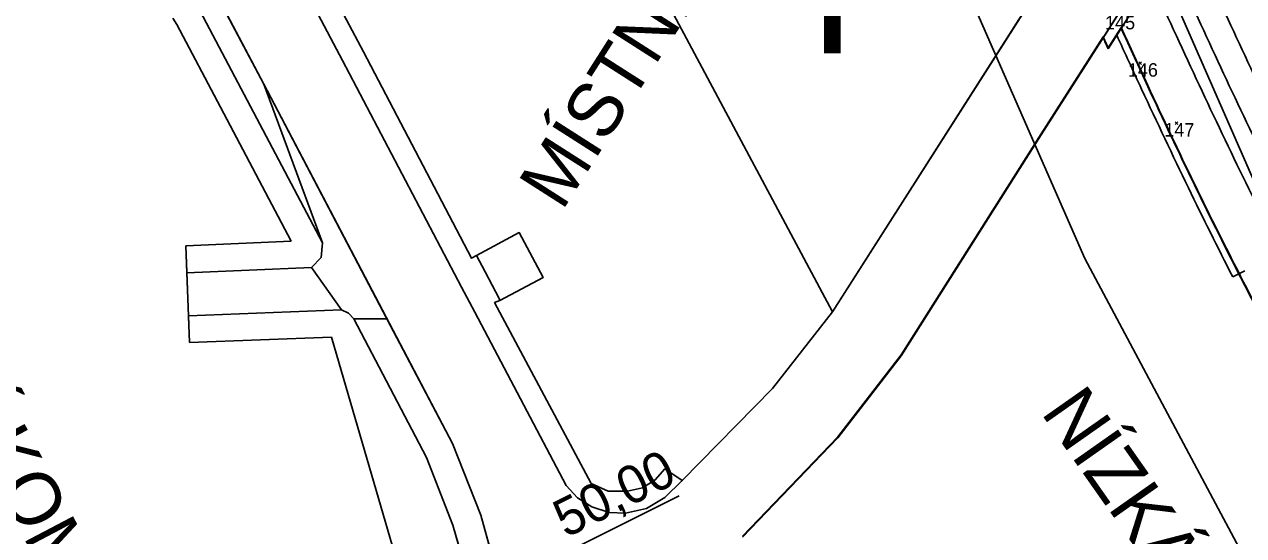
# Model space of a CAD drawing. Extents: x -606444 to -604546, y -1158114 to -1156869.
# Drawn here: x -605195.8 to -605105.4, y -1157370.5 to -1157332.6 of the extents above; entities that cross this region are included whole.
import ezdxf

# ---------------------------------------------------------------- set-up
doc = ezdxf.new("R2010")
doc.units = 0
for name, color, linetype in [('B_CHOD', 7, 'Continuous'), ('B_TRAM', 7, 'Continuous'), ('B_VOZ', 7, 'Continuous'), ('B_ZELEN', 7, 'Continuous'), ('geofyzikální profily_předběžný GTP', 7, 'Continuous'), ('NS_VB', 7, 'Continuous'), ('NS_VB_OBJ', 7, 'Continuous'), ('NS_VB_POP', 7, 'Continuous'), ('OSA', 7, 'Continuous'), ('OSAPOP', 7, 'Continuous'), ('podélný profil trasou tramvaje', 7, 'Continuous'), ('stabilitní profily_předběžný GTP', 7, 'Continuous')]:
    doc.layers.add(name, color=color, linetype=linetype)

msp = doc.modelspace()

# ---------------------------------------------------------------- linework, layer by layer
for p, q in [((-605113.04, -1157335.43), (-605113.14, -1157335.33)), ((-605113.04, -1157335.43), (-605113.14, -1157335.53)), ((-605113.04, -1157335.43), (-605112.94, -1157335.33)), ((-605113.04, -1157335.43), (-605112.94, -1157335.53)), ((-605110.36, -1157339.87), (-605110.46, -1157339.77)), ((-605110.36, -1157339.87), (-605110.46, -1157339.97)), ((-605110.36, -1157339.87), (-605110.26, -1157339.77)), ((-605110.36, -1157339.87), (-605110.26, -1157339.97))]:
    msp.add_line(p, q)
at = {"layer": 'B_CHOD'}
for points in [[(-605179.53, -1157337.76), (-605173.71, -1157348.76), (-605178.07, -1157336.98), (-605182.29, -1157328.99), (-605188.69, -1157318.53), (-605191.523, -1157314.683), (-605192.834, -1157315.649), (-605190.17, -1157319.29), (-605183.11, -1157331.05), (-605182.79, -1157331.58), (-605179.53, -1157337.76)], [(-605110.093, -1157324.593), (-605115.8, -1157333.547)], [(-605115.427, -1157334.358), (-605109.46, -1157324.996)], [(-605160.95, -1157353.18), (-605160.55, -1157353.02), (-605160.62, -1157352.89), (-605161.66, -1157350.91), (-605162.3, -1157349.7), (-605162.66, -1157349.9), (-605170.68, -1157334.59), (-605172.783, -1157330.604)], [(-605174.263, -1157331.396), (-605172.24, -1157335.22), (-605163.4, -1157352.04), (-605162.42, -1157353.9), (-605155.63, -1157366.76), (-605154.79, -1157367.67), (-605153.74, -1157368.34), (-605152.44, -1157368.76), (-605151.23, -1157368.79), (-605149.67, -1157368.45), (-605148.32, -1157367.65), (-605147.03, -1157366.39), (-605148.31, -1157365.52), (-605149.03, -1157366.34), (-605149.97, -1157366.92), (-605151.083, -1157367.17), (-605152.52, -1157367.17), (-605153.78, -1157366.59), (-605160.95, -1157353.18)], [(-605173.82, -1157349.84), (-605174.53, -1157350.57), (-605172.3, -1157353.72), (-605171.79, -1157353.96), (-605171.4, -1157354.38), (-605168.939, -1157354.38), (-605178.07, -1157336.98), (-605173.71, -1157348.76), (-605173.82, -1157349.84)], [(-605157.35, -1157351.33), (-605159.13, -1157347.99), (-605162.3, -1157349.7), (-605161.66, -1157350.91), (-605160.62, -1157352.89), (-605160.55, -1157353.02), (-605157.35, -1157351.33)], [(-605183.658, -1157354.155), (-605172.3, -1157353.72), (-605174.53, -1157350.57), (-605183.78, -1157350.98), (-605183.658, -1157354.155)], [(-605164.08, -1157363.64), (-605168.939, -1157354.38), (-605171.4, -1157354.38), (-605166.01, -1157364.66), (-605164.04, -1157369.69), (-605162.76, -1157374.11)], [(-605160.55, -1157374.03), (-605161.97, -1157368.95), (-605164.08, -1157363.64)]]:
    msp.add_lwpolyline(points, dxfattribs=at)
msp.add_arc((-604045.754, -1156842.066), 1177.52, 204.669736, 204.713151, dxfattribs=at)
at = {"layer": 'B_TRAM'}
msp.add_line((-605114.467, -1157332.852), (-605109.46, -1157324.996), dxfattribs=at)
for centre, radius, start, end in [((-603789.869, -1156724.367), 1457.674, 204.672767, 204.858777), ((-604698.868, -1157145.516), 455.853, 204.85878, 205.87559), ((-604812.368, -1157200.569), 329.706, 205.87559, 207.29075), ((-604908.165, -1157249.994), 221.911, 207.29075, 209.40677)]:
    msp.add_arc(centre, radius, start, end, dxfattribs=at)
at = {"layer": 'B_VOZ'}
for points in [[(-605186.716, -1157311.143), (-605191.523, -1157314.683), (-605188.69, -1157318.53), (-605182.29, -1157328.99), (-605178.07, -1157336.98), (-605164.08, -1157363.64), (-605161.97, -1157368.95), (-605160.55, -1157374.03)], [(-605107.824, -1157321.827), (-605110.697, -1157314.376), (-605135.867, -1157353.871), (-605140.32, -1157359.56), (-605147.03, -1157366.39), (-605148.32, -1157367.65), (-605149.67, -1157368.45), (-605151.23, -1157368.79), (-605152.44, -1157368.76), (-605153.74, -1157368.34), (-605154.79, -1157367.67), (-605155.63, -1157366.76), (-605162.42, -1157353.9), (-605163.4, -1157352.04), (-605172.24, -1157335.22), (-605174.263, -1157331.396)], [(-605142.56, -1157370.59), (-605135.48, -1157363.22), (-605130.78, -1157357.13), (-605120.39, -1157340.75), (-605110.093, -1157324.593)]]:
    msp.add_lwpolyline(points, dxfattribs=at)
at = {"layer": 'B_ZELEN'}
for p, q in [((-605179.53, -1157337.76), (-605182.79, -1157331.58)), ((-605184.823, -1157332.082), (-605184.532, -1157332.564)), ((-605184.532, -1157332.564), (-605181.298, -1157338.694)), ((-605115.426, -1157334.283), (-605114.467, -1157332.778)), ((-605120.389, -1157340.675), (-605115.799, -1157333.473)), ((-605115.799, -1157333.473), (-605115.426, -1157334.283)), ((-605173.71, -1157348.76), (-605179.53, -1157337.76)), ((-605181.298, -1157338.694), (-605176.039, -1157348.635)), ((-605130.779, -1157357.055), (-605120.389, -1157340.675)), ((-605176.039, -1157348.635), (-605183.857, -1157348.981)), ((-605183.857, -1157348.981), (-605183.78, -1157350.98)), ((-605173.82, -1157349.84), (-605173.71, -1157348.76)), ((-605174.53, -1157350.57), (-605173.82, -1157349.84)), ((-605183.78, -1157350.98), (-605174.53, -1157350.57)), ((-605172.3, -1157353.72), (-605183.658, -1157354.155)), ((-605183.658, -1157354.155), (-605183.582, -1157356.154)), ((-605171.79, -1157353.96), (-605172.3, -1157353.72)), ((-605171.4, -1157354.38), (-605171.79, -1157353.96)), ((-605166.01, -1157364.66), (-605171.4, -1157354.38)), ((-605183.582, -1157356.154), (-605173.042, -1157355.75)), ((-605173.042, -1157355.75), (-605167.056, -1157376.238)), ((-605135.479, -1157363.145), (-605130.779, -1157357.055)), ((-605142.559, -1157370.515), (-605135.479, -1157363.145)), ((-605164.04, -1157369.69), (-605166.01, -1157364.66)), ((-605162.76, -1157374.11), (-605164.04, -1157369.69))]:
    msp.add_line(p, q, dxfattribs=at)
for points in [[(-605156.956, -1157314.418), (-605135.867, -1157353.871), (-605118.771, -1157327.046), (-605119.142, -1157326.233), (-605118.182, -1157324.725), (-605145.901, -1157264.009), (-605144.283, -1157284.607)], [(-605140.32, -1157359.56), (-605135.867, -1157353.871), (-605156.956, -1157314.418), (-605169.829, -1157321.13)], [(-605172.783, -1157330.604), (-605170.68, -1157334.59), (-605162.66, -1157349.9), (-605162.3, -1157349.7), (-605159.13, -1157347.99), (-605157.35, -1157351.33), (-605160.55, -1157353.02), (-605160.95, -1157353.18), (-605153.78, -1157366.59), (-605152.52, -1157367.17), (-605151.083, -1157367.17), (-605149.97, -1157366.92), (-605149.03, -1157366.34), (-605148.31, -1157365.52), (-605147.03, -1157366.39), (-605140.32, -1157359.56)]]:
    msp.add_lwpolyline(points, dxfattribs=at)
for centre, radius, start, end in [((-603124.644, -1156416.743), 2190.552, 204.719463, 204.843219), ((-604711.097, -1157151.24), 442.318, 204.84322, 205.89115), ((-604805.738, -1157197.177), 337.118, 205.89115, 207.2752), ((-604910.994, -1157251.446), 218.695, 207.2752, 209.42233)]:
    msp.add_arc(centre, radius, start, end, dxfattribs=at)
at = {"layer": 'geofyzikální profily_předběžný GTP'}
msp.add_lwpolyline([(-605668.887, -1157175.563), (-605638.047, -1157172.713), (-605616.091, -1157172.842), (-605512.92, -1157173.16), (-605468.488, -1157175.648), (-605413.499, -1157174.062), (-605313.444, -1157169.44), (-605274.571, -1157178.007), (-605221.389, -1157204.274), (-605178.573, -1157224.003), (-605160.32, -1157243.281), (-605143.644, -1157289.502), (-605117.165, -1157349.927), (-605096.208, -1157389.159), (-605065.898, -1157426.812), (-605053.52, -1157443.58), (-605045.82, -1157465.15), (-605020.205, -1157502.195)], dxfattribs=at)
at = {"layer": 'NS_VB'}
for p, q in [((-605135.867, -1157353.871), (-605110.697, -1157314.376)), ((-605120.39, -1157340.75), (-605110.093, -1157324.593)), ((-605115.427, -1157334.358), (-605109.46, -1157324.996)), ((-605182.29, -1157328.99), (-605178.07, -1157336.98)), ((-605172.778, -1157330.613), (-605170.68, -1157334.59)), ((-605179.53, -1157337.76), (-605182.79, -1157331.58)), ((-605172.24, -1157335.22), (-605174.263, -1157331.396)), ((-605184.532, -1157332.564), (-605184.823, -1157332.082)), ((-605181.298, -1157338.694), (-605184.532, -1157332.564)), ((-605170.68, -1157334.59), (-605162.66, -1157349.9)), ((-605163.4, -1157352.04), (-605172.24, -1157335.22)), ((-605178.07, -1157336.98), (-605164.08, -1157363.64)), ((-605173.71, -1157348.76), (-605179.53, -1157337.76)), ((-605176.039, -1157348.635), (-605181.298, -1157338.694)), ((-605120.39, -1157340.75), (-605130.78, -1157357.13)), ((-605162.3, -1157349.7), (-605159.13, -1157347.99)), ((-605159.13, -1157347.99), (-605157.35, -1157351.33)), ((-605183.857, -1157348.981), (-605176.039, -1157348.635)), ((-605183.857, -1157348.981), (-605183.582, -1157356.154)), ((-605173.82, -1157349.84), (-605173.71, -1157348.76)), ((-605174.53, -1157350.57), (-605173.82, -1157349.84)), ((-605162.66, -1157349.9), (-605162.3, -1157349.7)), ((-605162.3, -1157349.7), (-605161.66, -1157350.91)), ((-605183.78, -1157350.98), (-605174.53, -1157350.57)), ((-605161.66, -1157350.91), (-605160.62, -1157352.89)), ((-605157.35, -1157351.33), (-605160.55, -1157353.02)), ((-605162.42, -1157353.9), (-605163.4, -1157352.04)), ((-605160.55, -1157353.02), (-605160.95, -1157353.18)), ((-605160.95, -1157353.18), (-605153.78, -1157366.59)), ((-605160.62, -1157352.89), (-605160.55, -1157353.02)), ((-605172.3, -1157353.72), (-605183.658, -1157354.155)), ((-605171.79, -1157353.96), (-605172.3, -1157353.72)), ((-605171.4, -1157354.38), (-605171.79, -1157353.96)), ((-605166.01, -1157364.66), (-605171.4, -1157354.38)), ((-605155.63, -1157366.76), (-605162.42, -1157353.9)), ((-605135.867, -1157353.871), (-605140.32, -1157359.56)), ((-605173.042, -1157355.75), (-605183.582, -1157356.154)), ((-605173.042, -1157355.75), (-605167.056, -1157376.238)), ((-605130.78, -1157357.13), (-605135.48, -1157363.22)), ((-605140.32, -1157359.56), (-605147.03, -1157366.39)), ((-605135.48, -1157363.22), (-605142.56, -1157370.59)), ((-605164.08, -1157363.64), (-605161.97, -1157368.95)), ((-605164.04, -1157369.69), (-605166.01, -1157364.66)), ((-605149.03, -1157366.34), (-605148.31, -1157365.52)), ((-605148.31, -1157365.52), (-605147.03, -1157366.39)), ((-605154.79, -1157367.67), (-605155.63, -1157366.76)), ((-605153.78, -1157366.59), (-605152.52, -1157367.17)), ((-605152.52, -1157367.17), (-605151.083, -1157367.17)), ((-605151.083, -1157367.17), (-605149.97, -1157366.92)), ((-605149.97, -1157366.92), (-605149.03, -1157366.34)), ((-605147.03, -1157366.39), (-605148.32, -1157367.65)), ((-605153.74, -1157368.34), (-605154.79, -1157367.67)), ((-605148.32, -1157367.65), (-605149.67, -1157368.45)), ((-605161.97, -1157368.95), (-605160.55, -1157374.03)), ((-605152.44, -1157368.76), (-605153.74, -1157368.34)), ((-605151.23, -1157368.79), (-605152.44, -1157368.76)), ((-605149.67, -1157368.45), (-605151.23, -1157368.79)), ((-605162.76, -1157374.11), (-605164.04, -1157369.69))]:
    msp.add_line(p, q, dxfattribs=at)
for centre, radius, start, end in [((-604045.754, -1156842.066), 1177.52, 204.669736, 204.713151), ((-604045.754, -1156842.066), 1176.02, 204.666083, 204.896591), ((-604665.748, -1157129.813), 492.506, 204.89659, 205.83778), ((-604827.34, -1157208.061), 312.965, 205.83778, 207.32857), ((-604900.916, -1157246.083), 230.146, 207.32857, 209.36895)]:
    msp.add_arc(centre, radius, start, end, dxfattribs=at)
at = {"layer": 'NS_VB_OBJ'}
msp.add_lwpolyline([(-605106.176, -1157351.278), (-605105.286, -1157350.821)], dxfattribs=at)
for centre, radius, start, end in [((-604045.754, -1156842.066), 1176.52, 204.681788, 204.896591), ((-604665.748, -1157129.813), 493.006, 204.89659, 205.83778), ((-604827.34, -1157208.061), 313.465, 205.83778, 207.18615)]:
    msp.add_arc(centre, radius, start, end, dxfattribs=at)
at = {"layer": 'OSA'}
for centre, radius, start, end in [((-604045.754, -1156842.066), 1168.52, 204.504959, 204.896591), ((-604045.754, -1156842.066), 1170.52, 204.504996, 204.896591), ((-604045.754, -1156842.066), 1172.52, 204.505033, 204.896591), ((-604665.748, -1157129.813), 485.006, 204.89659, 205.83778), ((-604665.748, -1157129.813), 487.006, 204.89659, 205.83778), ((-604665.748, -1157129.813), 489.006, 204.89659, 205.83778), ((-604827.34, -1157208.061), 309.465, 205.83778, 207.32857)]:
    msp.add_arc(centre, radius, start, end, dxfattribs=at)
at = {"layer": 'OSAPOP'}
msp.add_line((-605156.216, -1157371.985), (-605147.265, -1157367.527), dxfattribs=at)
at = {"layer": 'podélný profil trasou tramvaje'}
msp.add_lwpolyline([(-605085.67, -1157373.96), (-605102.483, -1157348.991), (-605137.415, -1157269.352), (-605142.94, -1157257.48), (-605148.09, -1157246.14), (-605156.56, -1157230.62), (-605167.27, -1157214.45), (-605176.96, -1157202.08), (-605190.28, -1157187.63), (-605201.93, -1157176.87), (-605210.19, -1157170.251), (-605214.51, -1157166.83), (-605234.53, -1157153.68), (-605243.13, -1157148.91), (-605255.42, -1157142.97), (-605270.4, -1157136.88), (-605273.539, -1157135.893), (-605289.22, -1157131.03), (-605304.97, -1157127.5), (-605318.55, -1157125.25), (-605341.868, -1157123.876), (-605358.234, -1157124.224), (-605590.305, -1157143.817)], dxfattribs=at)

# ---------------------------------------------------------------- texts
for s, p in [('145', (-605115.658, -1157332.92)), ('146', (-605113.965, -1157336.43)), ('147', (-605111.258, -1157340.87))]:
    msp.add_text(s, height=1).set_placement(p)
at = {"layer": 'NS_VB_POP'}
for s, rotation, p in [('MÍSTNÍ KOMUNIKACE DL. 85,00 m', 57.44727, (-605155.944, -1157346.456)), ('MÍSTNÍ KOMUNIKACE DL. 122,00 m', 297.70257, (-605208.681, -1157346.292)), ('NÍZKÁ PROTIHLUKOVÁ STĚNA DL. 56,00 m', 305.08639, (-605120.474, -1157361.331))]:
    msp.add_text(s, height=4, rotation=rotation, dxfattribs=at).set_placement(p)
at = {"layer": 'OSAPOP'}
msp.add_text('50,00', height=2.8, rotation=26.47488, dxfattribs=at).set_placement((-605155.666, -1157370.668))
at = {"layer": 'stabilitní profily_předběžný GTP'}
msp.add_text('I', height=10, dxfattribs=at).set_placement((-605137.749, -1157334.707))

doc.saveas('drawing.dxf')
